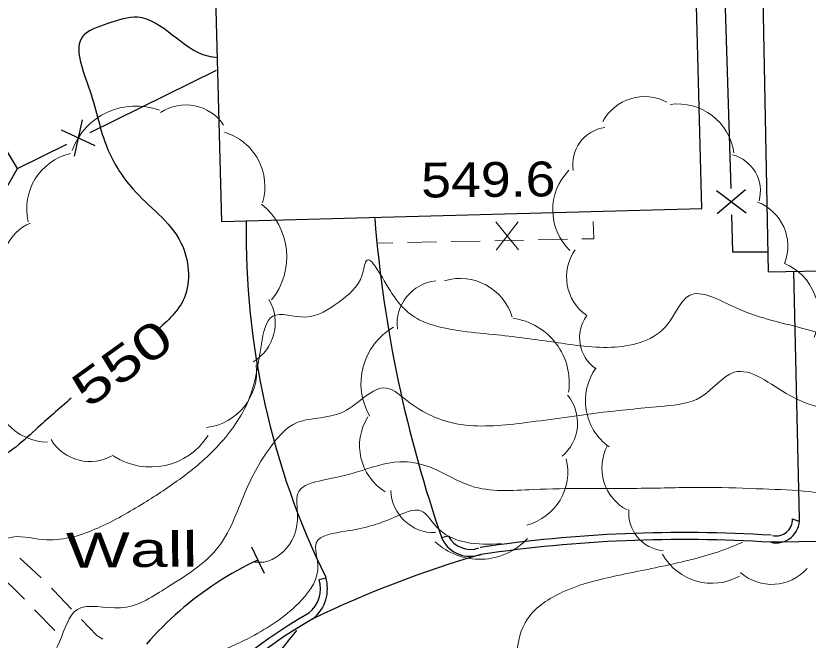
# Model space of a CAD drawing. Extents: x 2361708 to 2370558, y 6977955 to 6991887.
# Drawn here: x 2366646.4 to 2366755.4, y 6984050.5 to 6984136.5 of the extents above; entities that cross this region are included whole.
import ezdxf
from ezdxf.enums import TextEntityAlignment as Align

# ---------------------------------------------------------------- set-up
doc = ezdxf.new("R2010")
doc.units = 0
doc.header["$LTSCALE"] = 1.9
for name, color, linetype, lineweight in [('11', 7, 'Continuous', 25), ('13', 7, 'Continuous', 13), ('17', 7, 'Continuous', 25), ('18', 7, 'Continuous', 25), ('2', 7, 'Continuous', 25), ('29', 7, 'Continuous', 13), ('31', 7, 'Continuous', 13), ('35', 7, 'Continuous', 13)]:
    doc.layers.add(name, color=color, linetype=linetype, lineweight=lineweight)

msp = doc.modelspace()

# ---------------------------------------------------------------- linework, layer by layer
at = {"layer": '11'}
msp.add_lwpolyline([(2366674.737, 6984108.179), (2366740.803, 6984109.957), (2366739.721, 6984150.129), (2366708.028, 6984149.277), (2366707.777, 6984158.816), (2366673.404, 6984157.898)], close=True, dxfattribs=at)
msp.add_lwpolyline([(2366749.031, 6984146.037), (2366749.897, 6984101.224), (2366812.829, 6984102.433), (2366811.96, 6984147.476), (2366808.681, 6984147.415), (2366808.495, 6984157.414), (2366795.607, 6984157.181), (2366795.58, 6984158.981), (2366776.022, 6984158.665)], dxfattribs=at)
at = {"layer": '13'}
for p, q in [((2366718.294, 6984105.633), (2366722.293, 6984105.721)), ((2366696.297, 6984105.204), (2366698.297, 6984105.243)), ((2366700.296, 6984105.282), (2366704.296, 6984105.36)), ((2366706.296, 6984105.399), (2366710.295, 6984105.477)), ((2366712.294, 6984105.516), (2366716.294, 6984105.594)), ((2366651.812, 6984051.848), (2366649.025, 6984054.721))]:
    msp.add_line(p, q, dxfattribs=at)
for points in [[(2366724.293, 6984105.76), (2366725.923, 6984105.796), (2366725.84, 6984108.165)], [(2366649.913, 6984059.11), (2366648.531, 6984060.417), (2366646.987, 6984061.832)], [(2366647.641, 6984056.168), (2366647.409, 6984056.406), (2366646.308, 6984057.516), (2366645.178, 6984058.615), (2366644.794, 6984058.971)], [(2366654.094, 6984054.81), (2366651.63, 6984057.397), (2366651.327, 6984057.693)], [(2366658.394, 6984050.651), (2366657.559, 6984051.182), (2366655.478, 6984053.363)]]:
    msp.add_lwpolyline(points, dxfattribs=at)
at = {"layer": '17'}
for p, q in [((2366742.917, 6984172.68), (2366744.757, 6984112.705)), ((2366656.67, 6984120.417), (2366674.049, 6984129.013)), ((2366646.676, 6984115.482), (2366638.894, 6984128.298)), ((2366654.491, 6984117.146), (2366655.594, 6984122.157)), ((2366657.368, 6984118.563), (2366652.726, 6984120.74)), ((2366742.79, 6984112.456), (2366746.889, 6984109.375)), ((2366742.89, 6984109.257), (2366746.789, 6984112.575))]:
    msp.add_line(p, q, dxfattribs=at)
for points in [[(2366642.938, 6984109.036), (2366646.676, 6984115.482), (2366653.445, 6984118.827)], [(2366744.862, 6984109.106), (2366745.021, 6984103.997), (2366749.771, 6984103.982)]]:
    msp.add_lwpolyline(points, dxfattribs=at)
at = {"layer": '18'}
for points in [[(2366678.854, 6984063.365), (2366679.721, 6984061.564), (2366680.588, 6984059.762)], [(2366679.721, 6984061.564), (2366678.995, 6984061.217), (2366678.268, 6984060.85), (2366677.562, 6984060.483), (2366676.845, 6984060.096), (2366676.149, 6984059.7), (2366675.453, 6984059.283), (2366674.766, 6984058.867), (2366674.091, 6984058.43), (2366673.415, 6984057.984), (2366672.749, 6984057.527), (2366672.094, 6984057.051), (2366671.448, 6984056.574), (2366670.803, 6984056.079), (2366670.178, 6984055.582), (2366669.563, 6984055.067), (2366668.947, 6984054.541), (2366668.343, 6984054.005), (2366667.748, 6984053.46), (2366667.163, 6984052.904), (2366666.589, 6984052.339), (2366666.024, 6984051.763), (2366665.469, 6984051.178), (2366664.935, 6984050.583), (2366664.401, 6984049.977)]]:
    msp.add_lwpolyline(points, dxfattribs=at)
at = {"layer": '2'}
for p, q in [((2366754.2, 6984067.283), (2366753.447, 6984101.257)), ((2366753.241, 6984067.234), (2366754.134, 6984066.893)), ((2366705.931, 6984064.863), (2366705.003, 6984064.615)), ((2366774.459, 6984064.416), (2366750.272, 6984064.005)), ((2366688.137, 6984058.904), (2366689.075, 6984059.113))]:
    msp.add_line(p, q, dxfattribs=at)
for centre, radius, start, end in [((2366785.082, 6984106.315), 106.967, 179.00523, 206.13817), ((2366872.217, 6984122.592), 176.967, 184.54869, 199.1924), ((2366751.001, 6984067.125), 3.204, 256.84538, 2.82419), ((2366751.001, 6984067.125), 2.244, 256.84538, 2.82419), ((2366738.251, 6983874.848), 190.499, 86.36399, 98.43589), ((2366708.956, 6984066.445), 4.37, 207.67864, 289.93012), ((2366708.956, 6984066.445), 3.41, 207.67864, 289.93012), ((2366738.251, 6983874.848), 189.539, 86.36399, 98.43589), ((2366751.957, 6983919.082), 149.148, 106.1601, 115.69094), ((2366684.022, 6984057.616), 4.312, 308.41953, 17.39309), ((2366684.022, 6984057.616), 5.272, 308.41953, 17.39309), ((2366727.071, 6983985.292), 79.904, 120.25187, 158.03898), ((2366727.071, 6983985.292), 78.944, 120.25187, 158.03898)]:
    msp.add_arc(centre, radius, start, end, dxfattribs=at)
at = {"layer": '29'}
for centre, radius, start, end in [((2366732.901, 6984118.856), 6.5, 61.92545, 151.92545), ((2366669.825, 6984117.975), 6.24, 33.81328, 123.81328), ((2366737.466, 6984116.56), 7.796, 7.65493, 97.65493), ((2366662.957, 6984114.699), 9.365, 69.78938, 159.78938), ((2366728.213, 6984115.988), 5.194, 98.73883, 188.73883), ((2366672.889, 6984112.971), 7.808, 343.40752, 73.40752), ((2366655.751, 6984109.936), 7.808, 103.29912, 193.29912), ((2366743.645, 6984112.345), 5.194, 344.95329, 74.95329), ((2366728.074, 6984109.765), 7.796, 135.67907, 225.67907), ((2366674.342, 6984103.287), 9.365, 320.90471, 50.90471), ((2366746.113, 6984104.773), 6.5, 339.15865, 69.15865), ((2366650.846, 6984102.189), 6.24, 112.55171, 202.55171), ((2366728.679, 6984100.54), 6.5, 145.06856, 235.06856), ((2366749.071, 6984095.247), 7.796, 337.09288, 67.09288), ((2366707.532, 6984092.845), 7.486, 16.55424, 106.55424), ((2366704.854, 6984094.056), 5.982, 96.23423, 186.23423), ((2366675.879, 6984094.211), 6.24, 300.84294, 30.84294), ((2366713.577, 6984085.956), 8.979, 351.89667, 81.89667), ((2366729.166, 6984092.173), 5.194, 144.58082, 234.58082), ((2366702.885, 6984085.866), 8.979, 120.1679, 210.1679), ((2366671.753, 6984087.556), 7.808, 276.6322, 6.6322), ((2366732.569, 6984083.476), 7.796, 144.35754, 234.35754), ((2366650.996, 6984085.597), 7.808, 178.39809, 268.39809), ((2366717.715, 6984080.433), 5.982, 309.92846, 39.92846), ((2366701.199, 6984077.305), 7.486, 147.92758, 237.92758), ((2366664.987, 6984083.737), 9.365, 237.35866, 327.35866), ((2366656.63, 6984081.364), 6.24, 211.07245, 301.07245), ((2366733.53, 6984074.225), 6.5, 152.15922, 242.15922), ((2366714.856, 6984073.635), 7.486, 284.34666, 14.34666), ((2366703.994, 6984071.311), 5.982, 181.76926, 271.76926), ((2366735.925, 6984068.031), 5.194, 174.82747, 264.82747), ((2366710.235, 6984070.649), 8.979, 226.94338, 316.94338), ((2366742.191, 6984066.16), 7.796, 209.14561, 299.14561), ((2366750.406, 6984064.711), 6.5, 228.56483, 318.56483)]:
    msp.add_arc(centre, radius, start, end, dxfattribs=at)
at = {"layer": '31'}
for p, q in [((2366715.577, 6984104.257), (2366712.46, 6984108.108)), ((2366712.497, 6984104.228), (2366715.54, 6984108.137))]:
    msp.add_line(p, q, dxfattribs=at)
at = {"layer": '31', "lineweight": 25}
for points in [[(2366674.193, 6984130.704), (2366672.871, 6984130.922), (2366663.189, 6984136.29), (2366659.087, 6984135.411), (2366655.644, 6984133.658), (2366656.605, 6984126.217), (2366658.99, 6984118.329), (2366662.514, 6984112.663), (2366669.145, 6984105.235), (2366669.617, 6984097.689), (2366665.76, 6984093.102)], [(2366654.048, 6984083.83), (2366649.169, 6984079.514), (2366642.433, 6984074.909), (2366635.268, 6984073.291), (2366631.215, 6984066.182), (2366626.825, 6984056.71), (2366622.698, 6984049.04), (2366614.755, 6984039.804), (2366607.645, 6984031.366), (2366607.516, 6984031.255)], [(2366675.73, 6984020.684), (2366672.471, 6984020.583), (2366670.958, 6984026.178), (2366673.112, 6984034.12), (2366677.857, 6984042.075), (2366681.833, 6984047.723), (2366685.064, 6984051.874)]]:
    msp.add_spline(points, degree=3, dxfattribs=at)
at = {"layer": '35'}
for points in [[(2366939.585, 6984181.263), (2366938.892, 6984181.507), (2366931.873, 6984177.239), (2366927.212, 6984178.275), (2366921.502, 6984180.381), (2366914.675, 6984184.266), (2366909.2, 6984185.814), (2366900.054, 6984186.317), (2366890.937, 6984187.02), (2366878.681, 6984189.674), (2366869.885, 6984189.27), (2366859.968, 6984189.936), (2366851.726, 6984186.997), (2366844.317, 6984188.997), (2366836.691, 6984191.654), (2366830.142, 6984192.612), (2366821.826, 6984195.303), (2366815.826, 6984200.436), (2366807.065, 6984200.523), (2366797.628, 6984203.243), (2366791.581, 6984212.386), (2366787.468, 6984216.897), (2366779.676, 6984217.053), (2366773.295, 6984222.392), (2366767.534, 6984228.778), (2366767.41, 6984236.567), (2366763.633, 6984244.661), (2366757.814, 6984248.726), (2366750.89, 6984251.14), (2366740.935, 6984253.726), (2366733.666, 6984253.567), (2366724.931, 6984254.033), (2366715.39, 6984255.153), (2366704.499, 6984255.239), (2366694.976, 6984254.478), (2366687.392, 6984252.726), (2366678.56, 6984250.822), (2366669.627, 6984246.937), (2366662.889, 6984243.542), (2366655.577, 6984245.823), (2366648.4, 6984250.605), (2366637.395, 6984254.27), (2366631.732, 6984252.446), (2366626.413, 6984251.286), (2366625.381, 6984247.215), (2366628.041, 6984241.021), (2366626.452, 6984235.695), (2366619.357, 6984232.967), (2366609.942, 6984230.268), (2366608.943, 6984224.908), (2366608.892, 6984216.627), (2366602.614, 6984210.037), (2366599.251, 6984205.125), (2366600.895, 6984200.46), (2366599.004, 6984193.292), (2366594.321, 6984187.257), (2366584.587, 6984183.374), (2366573.015, 6984179.384), (2366563.98, 6984175.668), (2366556.332, 6984170.154), (2366547.197, 6984164.357), (2366543.606, 6984154.923), (2366538.836, 6984142.277), (2366533.34, 6984128.244), (2366530.729, 6984115.678), (2366528.162, 6984113.273), (2366525.444, 6984115.108), (2366525.179, 6984120.915), (2366523.698, 6984129.442), (2366521.828, 6984138.895), (2366520.104, 6984147.699), (2366520.496, 6984159.003), (2366519.468, 6984165.123), (2366517.415, 6984166.474), (2366515.49, 6984158.605), (2366512.753, 6984151.889), (2366507.856, 6984150.522), (2366501.793, 6984153.945), (2366491.507, 6984162.937), (2366486.399, 6984173.249), (2366481.652, 6984182.394), (2366478.876, 6984191.328), (2366478.669, 6984204.717), (2366479.328, 6984219.544), (2366480.289, 6984239.404), (2366481.375, 6984264.976), (2366483.202, 6984286.414), (2366485.119, 6984309.764), (2366487.058, 6984330.953), (2366488.671, 6984352.669), (2366489.501, 6984369.548), (2366489.972, 6984389.343), (2366490.856, 6984409.973), (2366492.166, 6984430.956)], [(2366748.755, 6984187.557), (2366747.005, 6984190.74), (2366748.07, 6984195.431), (2366753.384, 6984199.241), (2366752.842, 6984206.857), (2366743.985, 6984216.993), (2366738.528, 6984227.142), (2366732.878, 6984233.458), (2366722.291, 6984236.177), (2366713.996, 6984241.999), (2366705.74, 6984246.78), (2366696.072, 6984246.448), (2366693.058, 6984239.48), (2366695.447, 6984230.232), (2366692.764, 6984221.005), (2366687.181, 6984210.832), (2366681.047, 6984201.743), (2366672.633, 6984198.973), (2366666.797, 6984198.507), (2366660.365, 6984193.446), (2366650.181, 6984191.709), (2366644.86, 6984188.638), (2366643.699, 6984182.407), (2366641.603, 6984170.396), (2366639.051, 6984161.212), (2366634.696, 6984152.19), (2366633.527, 6984146.858), (2366634.263, 6984143.075), (2366633.074, 6984132.563), (2366626.375, 6984126.079), (2366621.173, 6984120.939)], [(2366840.992, 6984081.25), (2366837.906, 6984080.78), (2366834.18, 6984081.435), (2366831.218, 6984080.557), (2366830.782, 6984077.002), (2366824.837, 6984075.356), (2366819.988, 6984079.38), (2366815.262, 6984079.025), (2366808.856, 6984079.594), (2366798.598, 6984079.326), (2366794.422, 6984079.977), (2366790.866, 6984081.603), (2366782.784, 6984085.936), (2366776.618, 6984089.748), (2366771.395, 6984092.168), (2366767.497, 6984091.911), (2366760.044, 6984092.14), (2366753.919, 6984093.652), (2366745.424, 6984096.311), (2366739.087, 6984098), (2366736.036, 6984093.961), (2366728.845, 6984090.883), (2366720.498, 6984091.553), (2366712.107, 6984092.613), (2366702.881, 6984094.226), (2366698.173, 6984098.251), (2366694.62, 6984102.728), (2366694.068, 6984100.812), (2366690.844, 6984097.082), (2366686.253, 6984095.018), (2366681.762, 6984095.115), (2366680.208, 6984091.28), (2366678.422, 6984083.522), (2366674.33, 6984077.383), (2366668.945, 6984072.672), (2366663.738, 6984069.222), (2366657.31, 6984065.791), (2366650.183, 6984064.383), (2366645.351, 6984064.577), (2366643.019, 6984062.694), (2366642.3, 6984058.378), (2366640.682, 6984052.882), (2366635.885, 6984049.386), (2366633.394, 6984045.342), (2366629.54, 6984040.435)], [(2366828.645, 6984066.111), (2366823.918, 6984066.796), (2366813.927, 6984069.032), (2366804.498, 6984068.802), (2366797.607, 6984069.936), (2366786.675, 6984072.202), (2366779.535, 6984075.345), (2366774.21, 6984079.024), (2366768.39, 6984082.139), (2366762.02, 6984082.128), (2366752.869, 6984084.221), (2366745.238, 6984087.409), (2366740.621, 6984083.984), (2366735.612, 6984082.757), (2366727.2, 6984081.897), (2366716.623, 6984080.486), (2366707.755, 6984080.211), (2366700.646, 6984083.194), (2366697.377, 6984085.233), (2366691.508, 6984081.987), (2366684.584, 6984080.231), (2366681.977, 6984077.786), (2366678.168, 6984071.339), (2366674.403, 6984063.503), (2366666.899, 6984057.572), (2366660.813, 6984054.984), (2366654.905, 6984054.757), (2366652.447, 6984050.304), (2366649.605, 6984046.356), (2366645.707, 6984043.989), (2366642.9, 6984040.462)], [(2366781.588, 6984065.534), (2366777.404, 6984065.984), (2366772.802, 6984068.27), (2366770.779, 6984070.661), (2366764.001, 6984070.476), (2366755.575, 6984070.976), (2366749.212, 6984071.345), (2366741.659, 6984071.564), (2366733.56, 6984071.446), (2366724.79, 6984071.423), (2366717.591, 6984071.265), (2366709.026, 6984071.763), (2366703.18, 6984074.428), (2366699.243, 6984075.08), (2366693.227, 6984073.643), (2366688.677, 6984072.549), (2366685.342, 6984071.007), (2366685.168, 6984068.196), (2366684.386, 6984064.258), (2366680.524, 6984061.291), (2366679.284, 6984061.259)], [(2366713.252, 6984063.803), (2366708.32, 6984064.006), (2366704.208, 6984066.217), (2366702.218, 6984068.308), (2366698.427, 6984067.422), (2366691.784, 6984065.529), (2366687.759, 6984063.921), (2366687.968, 6984060.892), (2366685.724, 6984056.02), (2366679.26, 6984051.239), (2366673.603, 6984048.715), (2366668.276, 6984047.344), (2366665.152, 6984046.744), (2366663.662, 6984046.76)], [(2366751.166, 6984034.112), (2366745.26, 6984035.716), (2366735.69, 6984037.885), (2366727.569, 6984040.008), (2366718.858, 6984042.105), (2366716.081, 6984043.929), (2366715.298, 6984048.491), (2366716.8, 6984053.456), (2366721.685, 6984057.173), (2366729.224, 6984059.425), (2366737.458, 6984061.173), (2366744.867, 6984063.374), (2366746.401, 6984064.028)]]:
    msp.add_spline(points, degree=3, dxfattribs=at)

# ---------------------------------------------------------------- texts
at = {"layer": '18', "width": 1.45}
msp.add_text('Wall', height=4.8, rotation=0.545, dxfattribs=at).set_placement((2366653.37, 6984060.503))
at = {"layer": '31', "width": 1.15}
msp.add_text('549.6', height=4.8, rotation=0.545, dxfattribs=at).set_placement((2366702.207, 6984111.46))
at = {"layer": '31', "width": 1.4}
msp.add_text(' 550 ', height=4.8, rotation=35.838, dxfattribs=at).set_placement((2366662.453, 6984086.729), align=Align.CENTER)

doc.saveas('drawing.dxf')
